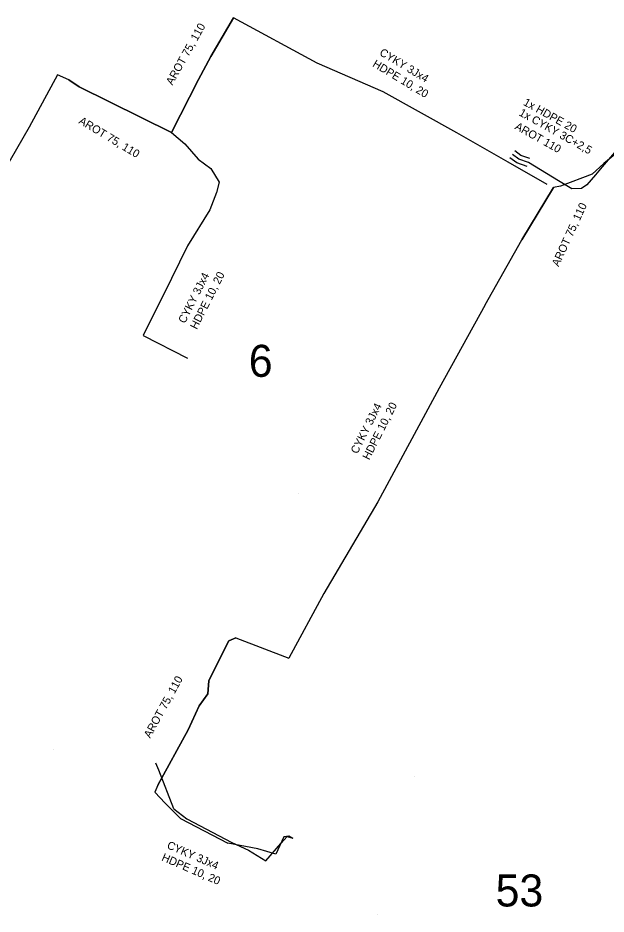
# Model space of a CAD drawing. Extents: x -651943 to -618711, y -1138561 to -1100552.
# Drawn here: x -642576.6 to -642521.5, y -1114386.4 to -1114302.4 of the extents above; entities that cross this region are included whole.
import ezdxf

# ---------------------------------------------------------------- set-up
doc = ezdxf.new("R2010")
doc.units = 0
for name, color, linetype in [('KT optika', 7, 'Continuous'), ('KT trasa', 7, 'Continuous'), ('KT zařízení', 7, 'Continuous'), ('SATT bloky', 7, 'Continuous'), ('SATT stanice', 7, 'Continuous')]:
    doc.layers.add(name, color=color, linetype=linetype)

# ---------------------------------------------------------------- blocks, each defined once
blk = doc.blocks.new('POINT_DISPLAY')
blk.add_line((0, 0), (0, 0))

msp = doc.modelspace()

# ---------------------------------------------------------------- linework, layer by layer
at = {"layer": 'KT optika'}
for p, q in [((-642558.5, -1114306.01), (-642556.39, -1114302.38)), ((-642548.54, -1114306.63), (-642556.39, -1114302.38)), ((-642559.66, -1114308.15), (-642558.5, -1114306.01)), ((-642542.36, -1114309.31), (-642548.54, -1114306.63)), ((-642572.88, -1114307.7), (-642575.55, -1114312.61)), ((-642571.81, -1114308.19), (-642572.88, -1114307.7)), ((-642562.2, -1114313.11), (-642559.66, -1114308.15)), ((-642571.81, -1114308.19), (-642570.86, -1114308.84)), ((-642570.86, -1114308.84), (-642562.2, -1114313.11)), ((-642535.46, -1114313.15), (-642542.36, -1114309.31)), ((-642575.55, -1114312.61), (-642578.78, -1114318.24)), ((-642562.2, -1114313.11), (-642560.93, -1114314.19)), ((-642530.64, -1114315.89), (-642535.46, -1114313.15)), ((-642560.93, -1114314.19), (-642559.71, -1114315.61)), ((-642520.3, -1114314.89), (-642521.67, -1114316.01)), ((-642559.71, -1114315.61), (-642558.5, -1114316.48)), ((-642529.64, -1114315.62), (-642530.24, -1114315.17)), ((-642528.74, -1114315.94), (-642529.64, -1114315.62)), ((-642520.67, -1114314.99), (-642521.83, -1114316.35)), ((-642558.5, -1114316.48), (-642557.73, -1114317.76)), ((-642526.98, -1114317.99), (-642530.64, -1114315.89)), ((-642525.91, -1114317.64), (-642528.74, -1114315.94)), ((-642521.67, -1114316.01), (-642522.78, -1114317.02)), ((-642521.83, -1114316.35), (-642522.47, -1114317.1)), ((-642522.78, -1114317.02), (-642525.75, -1114318.16)), ((-642522.47, -1114317.1), (-642523.27, -1114318.01)), ((-642557.73, -1114317.76), (-642557.97, -1114318.74)), ((-642525.75, -1114318.16), (-642526.4, -1114318.26)), ((-642524.67, -1114318.39), (-642525.91, -1114317.64)), ((-642523.27, -1114318.01), (-642523.78, -1114318.38)), ((-642557.97, -1114318.74), (-642558.59, -1114320.38)), ((-642529.36, -1114323.18), (-642526.4, -1114318.26)), ((-642523.78, -1114318.38), (-642524.67, -1114318.39)), ((-642558.59, -1114320.38), (-642560.71, -1114323.73)), ((-642532.79, -1114329.26), (-642529.36, -1114323.18)), ((-642560.71, -1114323.73), (-642562.21, -1114326.81)), ((-642562.21, -1114326.81), (-642564.85, -1114332.13)), ((-642532.79, -1114329.26), (-642537.12, -1114337.08)), ((-642564.85, -1114332.13), (-642560.708, -1114334.276)), ((-642537.12, -1114337.08), (-642542.87, -1114347.73)), ((-642542.87, -1114347.73), (-642547.93, -1114356.33)), ((-642547.93, -1114356.33), (-642551.19, -1114362.37)), ((-642557.38, -1114361.84), (-642556.83, -1114360.76)), ((-642556.83, -1114360.76), (-642556.18, -1114360.46)), ((-642556.18, -1114360.46), (-642551.19, -1114362.37)), ((-642558.7, -1114364.51), (-642557.38, -1114361.84)), ((-642558.8, -1114365.73), (-642558.7, -1114364.51)), ((-642559.6, -1114366.85), (-642558.8, -1114365.73)), ((-642560.63, -1114369.1), (-642559.6, -1114366.85)), ((-642563.49, -1114374.28), (-642560.63, -1114369.1)), ((-642563.49, -1114374.28), (-642563.76, -1114374.94)), ((-642563.76, -1114374.94), (-642562.8, -1114375.96)), ((-642562.8, -1114375.96), (-642561.36, -1114377.4)), ((-642561.36, -1114377.4), (-642556.9, -1114379.72)), ((-642551.68, -1114379.13), (-642552.42, -1114380.75)), ((-642551.21, -1114379.06), (-642551.68, -1114379.13)), ((-642550.827, -1114379.27), (-642551.21, -1114379.06)), ((-642554.11, -1114380.24), (-642556.9, -1114379.72)), ((-642552.42, -1114380.75), (-642554.11, -1114380.24))]:
    msp.add_line(p, q, dxfattribs=at)
at = {"layer": 'KT trasa'}
for p, q in [((-642558.5, -1114306.01), (-642556.39, -1114302.38)), ((-642548.54, -1114306.63), (-642556.39, -1114302.38)), ((-642559.66, -1114308.15), (-642558.5, -1114306.01)), ((-642542.36, -1114309.31), (-642548.54, -1114306.63)), ((-642572.88, -1114307.7), (-642575.55, -1114312.61)), ((-642571.81, -1114308.19), (-642572.88, -1114307.7)), ((-642562.2, -1114313.11), (-642559.66, -1114308.15)), ((-642571.81, -1114308.19), (-642570.86, -1114308.84)), ((-642570.86, -1114308.84), (-642562.2, -1114313.11)), ((-642535.46, -1114313.15), (-642542.36, -1114309.31)), ((-642575.55, -1114312.61), (-642578.78, -1114318.24)), ((-642562.2, -1114313.11), (-642560.93, -1114314.19)), ((-642530.64, -1114315.89), (-642535.46, -1114313.15)), ((-642560.93, -1114314.19), (-642559.71, -1114315.61)), ((-642520.3, -1114314.89), (-642521.67, -1114316.01)), ((-642559.71, -1114315.61), (-642558.5, -1114316.48)), ((-642529.64, -1114315.62), (-642530.24, -1114315.17)), ((-642528.74, -1114315.94), (-642529.64, -1114315.62)), ((-642520.67, -1114314.99), (-642521.83, -1114316.35)), ((-642558.5, -1114316.48), (-642557.73, -1114317.76)), ((-642526.98, -1114317.99), (-642530.64, -1114315.89)), ((-642525.91, -1114317.64), (-642528.74, -1114315.94)), ((-642521.67, -1114316.01), (-642522.78, -1114317.02)), ((-642521.83, -1114316.35), (-642522.47, -1114317.1)), ((-642522.78, -1114317.02), (-642525.75, -1114318.16)), ((-642522.47, -1114317.1), (-642523.27, -1114318.01)), ((-642557.73, -1114317.76), (-642557.97, -1114318.74)), ((-642525.75, -1114318.16), (-642526.4, -1114318.26)), ((-642524.67, -1114318.39), (-642525.91, -1114317.64)), ((-642523.27, -1114318.01), (-642523.78, -1114318.38)), ((-642557.97, -1114318.74), (-642558.59, -1114320.38)), ((-642529.36, -1114323.18), (-642526.4, -1114318.26)), ((-642523.78, -1114318.38), (-642524.67, -1114318.39)), ((-642558.59, -1114320.38), (-642560.71, -1114323.73)), ((-642532.79, -1114329.26), (-642529.36, -1114323.18)), ((-642560.71, -1114323.73), (-642562.21, -1114326.81)), ((-642562.21, -1114326.81), (-642564.85, -1114332.13)), ((-642532.79, -1114329.26), (-642537.12, -1114337.08)), ((-642564.85, -1114332.13), (-642560.708, -1114334.276)), ((-642537.12, -1114337.08), (-642542.87, -1114347.73)), ((-642542.87, -1114347.73), (-642547.93, -1114356.33)), ((-642547.93, -1114356.33), (-642551.19, -1114362.37)), ((-642557.38, -1114361.84), (-642556.83, -1114360.76)), ((-642556.83, -1114360.76), (-642556.18, -1114360.46)), ((-642556.18, -1114360.46), (-642551.19, -1114362.37)), ((-642558.7, -1114364.51), (-642557.38, -1114361.84)), ((-642558.8, -1114365.73), (-642558.7, -1114364.51)), ((-642559.6, -1114366.85), (-642558.8, -1114365.73)), ((-642560.63, -1114369.1), (-642559.6, -1114366.85)), ((-642563.49, -1114374.28), (-642560.63, -1114369.1)), ((-642563.396, -1114372.873), (-642563.659, -1114372.233)), ((-642561.962, -1114376.485), (-642563.396, -1114372.873)), ((-642563.49, -1114374.28), (-642563.76, -1114374.94)), ((-642563.76, -1114374.94), (-642562.8, -1114375.96)), ((-642562.8, -1114375.96), (-642561.36, -1114377.4)), ((-642561.962, -1114376.485), (-642560.743, -1114377.443)), ((-642561.36, -1114377.4), (-642556.9, -1114379.72)), ((-642560.743, -1114377.443), (-642556.553, -1114379.648)), ((-642551.68, -1114379.13), (-642552.42, -1114380.75)), ((-642551.943, -1114379.74), (-642551.343, -1114379.1)), ((-642551.21, -1114379.06), (-642551.68, -1114379.13)), ((-642551.343, -1114379.1), (-642550.814, -1114379.24)), ((-642550.827, -1114379.27), (-642551.21, -1114379.06)), ((-642554.11, -1114380.24), (-642556.9, -1114379.72)), ((-642556.553, -1114379.648), (-642554.963, -1114380.37)), ((-642554.963, -1114380.37), (-642553.343, -1114381.37)), ((-642552.42, -1114380.75), (-642554.11, -1114380.24)), ((-642553.343, -1114381.37), (-642551.943, -1114379.74))]:
    msp.add_line(p, q, dxfattribs=at)
at = {"layer": 'KT zařízení'}
for p, q in [((-642556.39, -1114302.38), (-642558.5, -1114306.01)), ((-642558.5, -1114306.01), (-642559.66, -1114308.15)), ((-642559.66, -1114308.15), (-642562.2, -1114313.11)), ((-642570.86, -1114308.84), (-642571.81, -1114308.19)), ((-642562.2, -1114313.11), (-642570.86, -1114308.84)), ((-642529.45, -1114315.263), (-642530, -1114314.85)), ((-642529.834, -1114315.975), (-642530.48, -1114315.49)), ((-642528.605, -1114315.563), (-642529.45, -1114315.263)), ((-642528.874, -1114316.316), (-642529.834, -1114315.975)), ((-642526.4, -1114318.26), (-642529.36, -1114323.18)), ((-642556.83, -1114360.76), (-642557.38, -1114361.84)), ((-642556.18, -1114360.46), (-642556.83, -1114360.76)), ((-642557.38, -1114361.84), (-642558.7, -1114364.51)), ((-642558.7, -1114364.51), (-642558.8, -1114365.73)), ((-642558.8, -1114365.73), (-642559.6, -1114366.85)), ((-642559.6, -1114366.85), (-642560.63, -1114369.1)), ((-642560.63, -1114369.1), (-642563.49, -1114374.28)), ((-642561.36, -1114377.4), (-642556.9, -1114379.72))]:
    msp.add_line(p, q, dxfattribs=at)

# ---------------------------------------------------------------- block references
at = {"layer": 'SATT stanice'}
for p in [(-642550.333, -1114346.959), (-642573.292, -1114370.935), (-642539.434, -1114373.473), (-642542.899, -1114386.363)]:
    msp.add_blockref('POINT_DISPLAY', p, dxfattribs=at)

# ---------------------------------------------------------------- texts
at = {"layer": 'KT zařízení'}
for s, height, rotation, p in [('AROT 75, 110 ', 0.74997, 60.74226, (-642562.116, -1114308.737)), ('CYKY 3Jx4', 0.75, 328.88879, (-642542.772, -1114305.816)), ('HDPE 10, 20', 0.74999, 328.88879, (-642543.416, -1114306.885)), ('1x HDPE 20', 0.75, 330.85605, (-642529.286, -1114310.504)), ('1x CYKY 3C+2,5', 0.75, 330.85605, (-642529.695, -1114311.477)), ('AROT 75, 110 ', 0.74996, 328.89674, (-642570.957, -1114312.222)), ('AROT 110', 0.75, 330.84995, (-642530.084, -1114312.762)), ('AROT 75, 110 ', 0.74997, 65.24473, (-642525.919, -1114325.744)), ('CYKY 3Jx4', 0.75, 63.12851, (-642560.94, -1114331.066)), ('HDPE 10, 20', 0.74998, 63.12851, (-642559.828, -1114331.63)), ('CYKY 3Jx4', 0.75, 63.12851, (-642544.78, -1114343.298)), ('HDPE 10, 20', 0.74998, 63.12851, (-642543.668, -1114343.862)), ('AROT 75, 110 ', 0.74996, 61.23377, (-642564.193, -1114369.931)), ('CYKY 3Jx4', 0.75, 336.53398, (-642562.688, -1114380.172)), ('HDPE 10, 20', 0.74998, 336.53398, (-642563.184, -1114381.316))]:
    msp.add_text(s, height=height, rotation=rotation, dxfattribs=at).set_placement(p)
at = {"layer": 'SATT bloky'}
for s, p in [('6', (-642554.951, -1114336.015)), ('53', (-642531.815, -1114385.65))]:
    msp.add_text(s, height=3, dxfattribs=at).set_placement(p)

doc.saveas('drawing.dxf')
